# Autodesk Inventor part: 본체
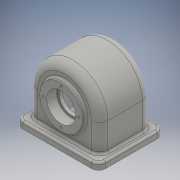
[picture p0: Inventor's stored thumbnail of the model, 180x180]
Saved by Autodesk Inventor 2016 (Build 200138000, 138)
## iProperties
Created: 2018-07
Part Number: 본체
Material: 일반
Document SubType Name: Modeling
Designer: 201-27
Density: 1 g/cm^3
Appearance: 기본값
Author: 201-27
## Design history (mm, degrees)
sketch "스케치1"
  geometry: L1 (-51, 0)-(51, 0); L2 (-51, 0)-(-51, 50); L3 (51, 0)-(51, 50); A1 r 51 centre (0, 50) between (51, 50) and (-51, 50); 2 further points
  constraints: 6 end point, 2 point on circle, 2 tangent, 2 vertical, 1 centre point, 1 coincident, 1 horizontal, 1 midpoint
  dimensions: "d1" = 50 distance of L1.start L2.end; "d2" = 102 distance of L1.start L1.end
extrude "돌출1" new body sketch "스케치1" stored distance "d3" = 74; taper "d4" = 0 deg
fillet "모깎기1" dims "d5" = 12
feature "쉘1" dims "d6" = 9
sketch "스케치2"
  geometry: L1 (-11, -10.5)-(89, -10.5); L2 (99, -0.5)-(99, 74.5); L3 (89, 84.5)-(-11, 84.5); L4 (-21, 74.5)-(-21, -0.5); L5 (-21, -10.5)-(99, 84.5); L6 (99, -10.5)-(-21, 84.5); L7 (0, 74)-(78, 74) reference; L8 (-12, 62)-(-12, 12) reference; L9 (78, 0)-(0, 0) reference; L10 (0, 65)-(78, 65) reference; L11 (81, 62)-(81, 12) reference; L12 (78, 9)-(0, 9) reference; L13 (-3, 12)-(-3, 62) reference; L14 (78, 0)-(0, 0) reference; L15 (90, 12)-(90, 62) reference; L16 (0, 74)-(78, 74) reference; L17 (-12, 62)-(-12, 12) reference; A1 r 10 centre (-11, 74.5) between (-11, 84.5) and (-21, 74.5); A2 r 10 centre (89, 74.5) between (99, 74.5) and (89, 84.5); A3 r 10 centre (89, -0.5) between (89, -10.5) and (99, -0.5); A4 r 10 centre (-11, -0.5) between (-21, -0.5) and (-11, -10.5); A5 r 12 centre (0, 62) between (0, 74) and (-12, 62) reference; A6 r 12 centre (0, 12) between (-12, 12) and (0, 0) reference; A7 r 3 centre (0, 62) between (0, 65) and (-3, 62) reference; A8 r 3 centre (78, 62) between (81, 62) and (78, 65) reference; A9 r 3 centre (78, 12) between (78, 9) and (81, 12) reference; A10 r 3 centre (0, 12) between (-3, 12) and (0, 9) reference; A11 r 12 centre (0, 12) between (-12, 12) and (0, 0) reference; A12 r 12 centre (78, 12) between (78, 0) and (90, 12) reference; A13 r 12 centre (78, 62) between (90, 62) and (78, 74) reference; A14 r 12 centre (0, 62) between (0, 74) and (-12, 62) reference; A15 r 12 centre (78, 12) between (78, 0) and (90, 12) reference; 1 further point
  constraints: 12 end point, 8 point on circle, 8 point on line, 8 tangent, 4 centre point, 3 equal radius, 2 midpoint, 2 parallel, 1 horizontal, 1 perpendicular
  dimensions: "d7" = 120 distance of L5.start L6.start; "d8" = 95 distance of L6.end L5.start; "d9" = 10 radius of A1
extrude "돌출2" join sketch "스케치2" distance "d10" = 10; taper "d11" = 0 deg
sketch "스케치3"
  geometry: L1 (50, 28)-(89, 28) reference; L2 (0, 28)-(50, 28) reference; L3 (50, 37)-(89, 37) reference; L4 (10, 37)-(50, 37) reference; L5 (50, -37)-(10, -37) reference; L6 (81, 22)-(50, 22); L7 (81, 22)-(81, 42); L8 (81, 42)-(50, 42); L9 (0, 0)-(101, 0); L10 (101, -25)-(101, 25) reference; L11 (50, 42)-(50, 22); L12 (0, -37.5)-(0, 37.5) reference; 3 further points
  constraints: 10 end point, 2 vertical, 1 midpoint, 1 perpendicular
  dimensions: "d13" = 6 distance between parallel lines of L1 L6; "d15" = 5 distance between parallel lines of L3 L8; "d17" = 50 distance between parallel lines of L12 L11; "d18" = 62 diameter of L7 L11
revolve "회전1" sketch "스케치3" stored, may be unused: angle "d19" = 90 deg
hole "구멍1" diameter "d22" = 29; stored, may be unused: countersink angle "d26" = 90 deg, drill point angle "d28" = 118 deg; dims "d23" = 6, "d24" = 35, "d25" = 15, "d27" = 8, "d74" = 10, "d75" = 10
sketch "스케치4"
  geometry: L1 (-50, -50)-(50, -50) reference; C1 r 31 at (0, 0) reference; 6 further points
  constraints: 1 midpoint, 1 vertical alignment, 5 other
  dimensions: "d31" = 26 distance of C1.centre point (0, 26); "d34" = 360 deg dimension on C1.centre point (0, 26) (derived)
hole "구멍2" sketch "스케치4" at (0, 26), (-26, 0), (0, -26), (26, 0) diameter "d36" = 3.242; stored, may be unused: countersink angle "d40" = 90 deg, drill point angle "d42" = 118 deg; dims "d37" = 8, "d38" = 21, "d39" = 15, "d41" = 10
fillet "모깎기2" dims "d43" = 3
chamfer "모따기1" distance "d44" = 1; stored, may be unused: second distance "d45" = 2, angle "d46" = 45 deg
hole "구멍3" diameter "d51" = 36; stored, may be unused: countersink angle "d55" = 90 deg, drill point angle "d57" = 118 deg; dims "d52" = 8, "d53" = 42, "d54" = 15, "d56" = 10, "d60" = 10, "d61" = 10
sketch "스케치6"
  geometry: C1 r 1.621 at (0, 26) reference; C2 r 31 at (0, 0) reference; 5 further points
  constraints: 1 coincident, 5 other
  dimensions: "d58" = 26 distance of point (0, 26) C2.centre (derived); "d65" = 360 deg dimension on C2.centre point (0, 26) (derived)
hole "구멍4" sketch "스케치6" at (0, 26), (-26, 0), (0, -26), (26, 0) diameter "d67" = 3.242; stored, may be unused: countersink angle "d71" = 90 deg, drill point angle "d73" = 118 deg; dims "d68" = 8, "d69" = 42, "d70" = 15, "d72" = 10
fillet "모깎기3" dims "d76" = 0.6
node "솔리드1"
mirror "대칭1"
node "투영된 루프1"
other parameters: "d16" = 62
